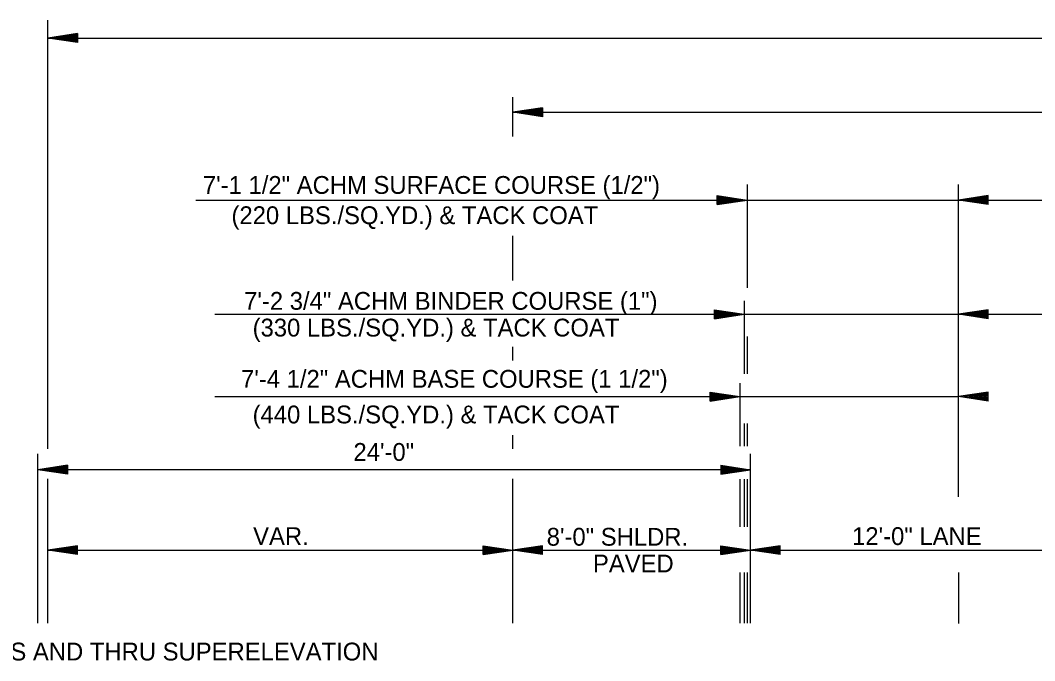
# Model space of a CAD drawing. Extents: x 1371763 to 1372860, y 385599 to 385872.
# Drawn here: x 1372517.33 to 1372551.49, y 385625.22 to 385646.79 of the extents above; entities that cross this region are included whole.
import ezdxf

# ---------------------------------------------------------------- set-up
doc = ezdxf.new("R2010")
doc.units = 0
doc.layers.add('R_Draft', color=7, linetype='Continuous')

msp = doc.modelspace()

# ---------------------------------------------------------------- linework, layer by layer
at = {"layer": 'R_Draft'}
for p, q in [((1372518.262, 385632.358), (1372518.262, 385646.792)), ((1372519.262, 385646.342), (1372518.262, 385646.192)), ((1372518.262, 385646.192), (1372597.103, 385646.192)), ((1372519.262, 385646.042), (1372518.262, 385646.192)), ((1372519.262, 385646.317), (1372518.429, 385646.192)), ((1372519.262, 385646.067), (1372518.429, 385646.192)), ((1372519.262, 385646.291), (1372518.601, 385646.192)), ((1372519.262, 385646.092), (1372518.601, 385646.192)), ((1372519.262, 385646.266), (1372518.767, 385646.192)), ((1372519.262, 385646.117), (1372518.767, 385646.192)), ((1372519.262, 385646.24), (1372518.937, 385646.192)), ((1372519.262, 385646.143), (1372518.937, 385646.192)), ((1372519.262, 385646.215), (1372519.104, 385646.192)), ((1372519.262, 385646.168), (1372519.104, 385646.192)), ((1372519.262, 385646.342), (1372519.262, 385646.042)), ((1372533.92, 385642.882), (1372533.92, 385644.202)), ((1372534.92, 385643.842), (1372533.92, 385643.692)), ((1372534.92, 385643.817), (1372534.087, 385643.692)), ((1372534.92, 385643.791), (1372534.259, 385643.692)), ((1372534.92, 385643.842), (1372534.92, 385643.542)), ((1372533.92, 385643.692), (1372585.92, 385643.692)), ((1372534.92, 385643.542), (1372533.92, 385643.692)), ((1372534.92, 385643.567), (1372534.087, 385643.692)), ((1372534.92, 385643.592), (1372534.259, 385643.692)), ((1372534.92, 385643.766), (1372534.425, 385643.692)), ((1372534.92, 385643.617), (1372534.425, 385643.692)), ((1372534.92, 385643.74), (1372534.595, 385643.692)), ((1372534.92, 385643.643), (1372534.595, 385643.692)), ((1372534.92, 385643.715), (1372534.762, 385643.692)), ((1372534.92, 385643.668), (1372534.762, 385643.692)), ((1372541.804, 385641.262), (1372541.804, 385637.779)), ((1372548.921, 385630.747), (1372548.923, 385641.262)), ((1372523.247, 385640.735), (1372548.923, 385640.736)), ((1372540.804, 385640.886), (1372541.804, 385640.736)), ((1372540.804, 385640.586), (1372540.804, 385640.886)), ((1372540.804, 385640.861), (1372541.637, 385640.736)), ((1372540.804, 385640.835), (1372541.465, 385640.736)), ((1372540.804, 385640.81), (1372541.298, 385640.736)), ((1372540.804, 385640.785), (1372541.129, 385640.736)), ((1372540.804, 385640.759), (1372540.962, 385640.736)), ((1372540.804, 385640.586), (1372541.804, 385640.736)), ((1372540.804, 385640.687), (1372541.129, 385640.736)), ((1372540.804, 385640.636), (1372541.465, 385640.736)), ((1372540.804, 385640.611), (1372541.637, 385640.736)), ((1372540.804, 385640.661), (1372541.298, 385640.736)), ((1372540.804, 385640.712), (1372540.962, 385640.736)), ((1372549.923, 385640.886), (1372548.923, 385640.736)), ((1372548.923, 385640.736), (1372570.923, 385640.736)), ((1372549.923, 385640.586), (1372548.923, 385640.736)), ((1372549.923, 385640.861), (1372549.09, 385640.736)), ((1372549.923, 385640.611), (1372549.09, 385640.736)), ((1372549.923, 385640.836), (1372549.262, 385640.736)), ((1372549.923, 385640.637), (1372549.262, 385640.736)), ((1372549.923, 385640.811), (1372549.428, 385640.736)), ((1372549.923, 385640.662), (1372549.428, 385640.736)), ((1372549.923, 385640.785), (1372549.598, 385640.736)), ((1372549.923, 385640.688), (1372549.598, 385640.736)), ((1372549.923, 385640.76), (1372549.765, 385640.736)), ((1372549.923, 385640.713), (1372549.765, 385640.736)), ((1372549.923, 385640.586), (1372549.923, 385640.886)), ((1372533.92, 385638.028), (1372533.92, 385639.528)), ((1372541.705, 385637.342), (1372541.705, 385634.89)), ((1372540.705, 385637.042), (1372541.705, 385636.892)), ((1372540.705, 385636.742), (1372540.705, 385637.042)), ((1372540.705, 385637.017), (1372541.538, 385636.892)), ((1372540.705, 385636.991), (1372541.366, 385636.892)), ((1372540.705, 385636.966), (1372541.199, 385636.892)), ((1372549.923, 385637.042), (1372548.923, 385636.892)), ((1372549.923, 385637.017), (1372549.09, 385636.892)), ((1372549.923, 385636.991), (1372549.262, 385636.892)), ((1372549.923, 385636.966), (1372549.428, 385636.892)), ((1372549.923, 385636.742), (1372549.923, 385637.042)), ((1372523.881, 385636.892), (1372548.923, 385636.892)), ((1372540.705, 385636.941), (1372541.03, 385636.892)), ((1372540.705, 385636.915), (1372540.863, 385636.892)), ((1372540.705, 385636.742), (1372541.705, 385636.892)), ((1372540.705, 385636.843), (1372541.03, 385636.892)), ((1372540.705, 385636.792), (1372541.366, 385636.892)), ((1372540.705, 385636.767), (1372541.538, 385636.892)), ((1372540.705, 385636.817), (1372541.199, 385636.892)), ((1372540.705, 385636.868), (1372540.863, 385636.892)), ((1372549.923, 385636.742), (1372548.923, 385636.892)), ((1372548.923, 385636.892), (1372570.923, 385636.892)), ((1372549.923, 385636.767), (1372549.09, 385636.892)), ((1372549.923, 385636.792), (1372549.262, 385636.892)), ((1372549.923, 385636.817), (1372549.428, 385636.892)), ((1372549.923, 385636.941), (1372549.598, 385636.892)), ((1372549.923, 385636.843), (1372549.598, 385636.892)), ((1372549.923, 385636.915), (1372549.765, 385636.892)), ((1372549.923, 385636.868), (1372549.765, 385636.892)), ((1372541.804, 385636.142), (1372541.804, 385634.89)), ((1372533.92, 385635.331), (1372533.92, 385635.796)), ((1372541.566, 385634.566), (1372541.566, 385632.451)), ((1372540.566, 385634.266), (1372541.566, 385634.116)), ((1372540.566, 385633.966), (1372540.566, 385634.266)), ((1372540.566, 385634.241), (1372541.399, 385634.116)), ((1372540.566, 385634.216), (1372541.227, 385634.116)), ((1372549.922, 385634.266), (1372548.922, 385634.116)), ((1372549.922, 385634.241), (1372549.089, 385634.116)), ((1372549.922, 385634.216), (1372549.261, 385634.116)), ((1372549.922, 385633.966), (1372549.922, 385634.266)), ((1372523.881, 385634.116), (1372548.923, 385634.116)), ((1372540.566, 385634.191), (1372541.06, 385634.116)), ((1372540.566, 385634.165), (1372540.891, 385634.116)), ((1372540.566, 385634.14), (1372540.724, 385634.116)), ((1372540.566, 385633.966), (1372541.566, 385634.116)), ((1372540.566, 385634.068), (1372540.891, 385634.116)), ((1372540.566, 385634.017), (1372541.227, 385634.116)), ((1372540.566, 385633.991), (1372541.399, 385634.116)), ((1372540.566, 385634.042), (1372541.06, 385634.116)), ((1372540.566, 385634.093), (1372540.724, 385634.116)), ((1372549.922, 385633.966), (1372548.922, 385634.116)), ((1372549.922, 385633.991), (1372549.089, 385634.116)), ((1372549.922, 385634.017), (1372549.261, 385634.116)), ((1372549.922, 385634.191), (1372549.427, 385634.116)), ((1372549.922, 385634.042), (1372549.427, 385634.116)), ((1372549.922, 385634.165), (1372549.597, 385634.116)), ((1372549.922, 385634.068), (1372549.597, 385634.116)), ((1372549.922, 385634.14), (1372549.764, 385634.116)), ((1372549.922, 385634.093), (1372549.764, 385634.116)), ((1372541.705, 385633.216), (1372541.705, 385632.451)), ((1372541.804, 385633.216), (1372541.804, 385632.451)), ((1372533.92, 385632.358), (1372533.92, 385632.823)), ((1372517.92, 385626.486), (1372517.92, 385632.194)), ((1372541.919, 385626.483), (1372541.92, 385632.194)), ((1372518.92, 385631.804), (1372517.92, 385631.654)), ((1372518.92, 385631.504), (1372517.92, 385631.654)), ((1372541.92, 385631.654), (1372517.92, 385631.654)), ((1372518.92, 385631.779), (1372518.087, 385631.654)), ((1372518.92, 385631.529), (1372518.087, 385631.654)), ((1372518.92, 385631.753), (1372518.259, 385631.654)), ((1372518.92, 385631.554), (1372518.259, 385631.654)), ((1372518.92, 385631.728), (1372518.425, 385631.654)), ((1372518.92, 385631.579), (1372518.425, 385631.654)), ((1372518.92, 385631.702), (1372518.595, 385631.654)), ((1372518.92, 385631.605), (1372518.595, 385631.654)), ((1372518.92, 385631.677), (1372518.762, 385631.654)), ((1372518.92, 385631.63), (1372518.762, 385631.654)), ((1372518.92, 385631.804), (1372518.92, 385631.504)), ((1372540.92, 385631.804), (1372541.92, 385631.654)), ((1372540.92, 385631.804), (1372540.92, 385631.504)), ((1372540.92, 385631.779), (1372541.753, 385631.654)), ((1372540.92, 385631.753), (1372541.581, 385631.654)), ((1372540.92, 385631.728), (1372541.414, 385631.654)), ((1372540.92, 385631.702), (1372541.245, 385631.654)), ((1372540.92, 385631.677), (1372541.078, 385631.654)), ((1372540.92, 385631.504), (1372541.92, 385631.654)), ((1372540.92, 385631.605), (1372541.245, 385631.654)), ((1372540.92, 385631.554), (1372541.581, 385631.654)), ((1372540.92, 385631.529), (1372541.753, 385631.654)), ((1372540.92, 385631.579), (1372541.414, 385631.654)), ((1372540.92, 385631.63), (1372541.078, 385631.654)), ((1372518.262, 385626.486), (1372518.262, 385631.345)), ((1372533.919, 385626.484), (1372533.92, 385631.344)), ((1372541.566, 385631.343), (1372541.566, 385629.734)), ((1372541.705, 385631.343), (1372541.705, 385629.734)), ((1372541.804, 385631.343), (1372541.804, 385629.734)), ((1372519.262, 385629.097), (1372518.262, 385628.947)), ((1372519.262, 385628.797), (1372519.262, 385629.097)), ((1372532.92, 385629.097), (1372533.92, 385628.947)), ((1372532.92, 385628.797), (1372532.92, 385629.097)), ((1372534.92, 385629.097), (1372533.92, 385628.947)), ((1372534.92, 385628.797), (1372534.92, 385629.097)), ((1372540.92, 385629.097), (1372541.92, 385628.947)), ((1372540.92, 385628.797), (1372540.92, 385629.097)), ((1372542.92, 385629.097), (1372541.92, 385628.947)), ((1372542.92, 385628.797), (1372542.92, 385629.097)), ((1372518.262, 385628.947), (1372533.92, 385628.947)), ((1372519.262, 385628.797), (1372518.262, 385628.947)), ((1372519.262, 385629.072), (1372518.429, 385628.947)), ((1372519.262, 385628.822), (1372518.429, 385628.947)), ((1372519.262, 385629.047), (1372518.601, 385628.947)), ((1372519.262, 385628.848), (1372518.601, 385628.947)), ((1372519.262, 385629.022), (1372518.767, 385628.947)), ((1372519.262, 385628.873), (1372518.767, 385628.947)), ((1372519.262, 385628.996), (1372518.937, 385628.947)), ((1372519.262, 385628.899), (1372518.937, 385628.947)), ((1372519.262, 385628.971), (1372519.104, 385628.947)), ((1372519.262, 385628.924), (1372519.104, 385628.947)), ((1372532.92, 385629.072), (1372533.753, 385628.947)), ((1372532.92, 385629.047), (1372533.581, 385628.947)), ((1372532.92, 385629.022), (1372533.414, 385628.947)), ((1372532.92, 385628.996), (1372533.245, 385628.947)), ((1372532.92, 385628.971), (1372533.078, 385628.947)), ((1372532.92, 385628.797), (1372533.92, 385628.947)), ((1372532.92, 385628.899), (1372533.245, 385628.947)), ((1372532.92, 385628.848), (1372533.581, 385628.947)), ((1372532.92, 385628.822), (1372533.753, 385628.947)), ((1372532.92, 385628.873), (1372533.414, 385628.947)), ((1372532.92, 385628.924), (1372533.078, 385628.947)), ((1372533.92, 385628.947), (1372541.92, 385628.947)), ((1372534.92, 385628.797), (1372533.92, 385628.947)), ((1372534.92, 385629.072), (1372534.087, 385628.947)), ((1372534.92, 385628.822), (1372534.087, 385628.947)), ((1372534.92, 385629.047), (1372534.259, 385628.947)), ((1372534.92, 385628.848), (1372534.259, 385628.947)), ((1372534.92, 385629.022), (1372534.425, 385628.947)), ((1372534.92, 385628.873), (1372534.425, 385628.947)), ((1372534.92, 385628.996), (1372534.595, 385628.947)), ((1372534.92, 385628.899), (1372534.595, 385628.947)), ((1372534.92, 385628.971), (1372534.762, 385628.947)), ((1372534.92, 385628.924), (1372534.762, 385628.947)), ((1372540.92, 385629.072), (1372541.753, 385628.947)), ((1372540.92, 385629.047), (1372541.581, 385628.947)), ((1372540.92, 385629.022), (1372541.414, 385628.947)), ((1372540.92, 385628.996), (1372541.245, 385628.947)), ((1372540.92, 385628.971), (1372541.078, 385628.947)), ((1372540.92, 385628.797), (1372541.92, 385628.947)), ((1372540.92, 385628.899), (1372541.245, 385628.947)), ((1372540.92, 385628.848), (1372541.581, 385628.947)), ((1372540.92, 385628.822), (1372541.753, 385628.947)), ((1372540.92, 385628.873), (1372541.414, 385628.947)), ((1372540.92, 385628.924), (1372541.078, 385628.947)), ((1372541.92, 385628.947), (1372553.92, 385628.947)), ((1372542.92, 385628.797), (1372541.92, 385628.947)), ((1372542.92, 385629.072), (1372542.087, 385628.947)), ((1372542.92, 385628.822), (1372542.087, 385628.947)), ((1372542.92, 385629.047), (1372542.259, 385628.947)), ((1372542.92, 385628.848), (1372542.259, 385628.947)), ((1372542.92, 385629.022), (1372542.425, 385628.947)), ((1372542.92, 385628.873), (1372542.425, 385628.947)), ((1372542.92, 385628.996), (1372542.595, 385628.947)), ((1372542.92, 385628.899), (1372542.595, 385628.947)), ((1372542.92, 385628.971), (1372542.762, 385628.947)), ((1372542.92, 385628.924), (1372542.762, 385628.947)), ((1372541.566, 385628.197), (1372541.566, 385626.483)), ((1372541.705, 385628.197), (1372541.705, 385626.483)), ((1372541.804, 385628.197), (1372541.804, 385626.483)), ((1372548.921, 385628.197), (1372548.921, 385626.482))]:
    msp.add_line(p, q, dxfattribs=at)

# ---------------------------------------------------------------- texts
for s, p in [('7\'-1 1/2" ACHM SURFACE COURSE (1/2")', (1372523.483, 385640.946)), ('(220 LBS./SQ.YD.) & TACK COAT', (1372524.445, 385639.926)), ('7\'-2 3/4" ACHM BINDER COURSE (1")', (1372524.871, 385637.042)), ('(330 LBS./SQ.YD.) & TACK COAT', (1372525.157, 385636.142)), ('7\'-4 1/2" ACHM BASE COURSE (1 1/2")', (1372524.767, 385634.416)), ('(440 LBS./SQ.YD.) & TACK COAT', (1372525.157, 385633.216)), ('24\'-0"', (1372528.552, 385631.954)), ('VAR.', (1372525.174, 385629.119)), ('8\'-0" SHLDR.', (1372535.059, 385629.097)), ('12\'-0" LANE', (1372545.342, 385629.119)), ('PAVED', (1372536.616, 385628.197))]:
    msp.add_text(s, height=0.6, rotation=360, dxfattribs=at).set_placement(p)
msp.add_text('ON ALL SUPERELEVATED CURVES AND THRU SUPERELEVATION', height=0.6, dxfattribs=at).set_placement((1372503.937, 385625.232))

doc.saveas('drawing.dxf')
